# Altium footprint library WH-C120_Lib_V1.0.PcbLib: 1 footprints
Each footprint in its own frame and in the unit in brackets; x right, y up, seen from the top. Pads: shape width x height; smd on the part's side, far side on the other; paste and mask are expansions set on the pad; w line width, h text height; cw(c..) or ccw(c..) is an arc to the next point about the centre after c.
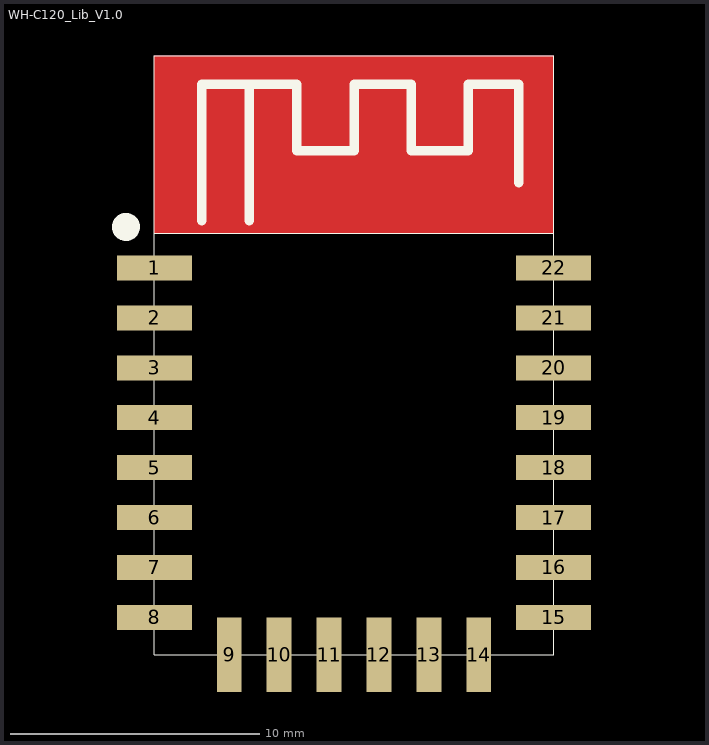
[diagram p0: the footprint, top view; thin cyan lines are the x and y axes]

## WH-C120_Lib_V1.0 [mm]
pads (22):
  rect 3x1 smd paste+0.05 mask+0.05: 1(-311.785,-665.22) 2(-311.785,-667.22) 3(-311.785,-669.22) 4(-311.785,-671.22) 5(-311.785,-673.22) 6(-311.785,-675.22) 7(-311.785,-677.22) 8(-311.785,-679.22) 15(-295.785,-679.22) 16(-295.785,-677.22) 17(-295.785,-675.22) 18(-295.785,-673.22) 19(-295.785,-671.22) 20(-295.785,-669.22) 21(-295.785,-667.22) 22(-295.785,-665.22)
  rect 1x3 smd paste+0.05 mask+0.05: 9(-308.785,-680.72) 10(-306.785,-680.72) 11(-304.785,-680.72) 12(-302.785,-680.72) 13(-300.785,-680.72) 14(-298.785,-680.72)
Top Layer:
  pour cut-out: -311.785,-656.717 -295.783,-656.717 -295.783,-663.829 -311.785,-663.829
Bottom Layer:
  pour cut-out: -311.785,-656.717 -295.783,-656.717 -295.783,-663.829 -311.785,-663.829
Top Overlay:
  circle w0.762: c-312.928,-663.575 r0.18
  lines w0.025: -311.785,-663.829 -295.785,-663.829 ; -311.785,-680.72 -311.785,-656.72 -295.785,-656.72 -295.785,-680.72 -311.785,-680.72
  lines w0.381: -309.88,-663.321 -309.88,-662.94 -309.88,-657.86 -306.07,-657.86 -306.07,-660.527 -303.784,-660.527 -303.784,-657.86 -301.498,-657.86 -301.498,-660.527 -299.212,-660.527 -299.212,-657.86 -297.18,-657.86 -297.18,-661.797 ; -307.975,-663.321 -307.975,-662.94 -307.975,-657.86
